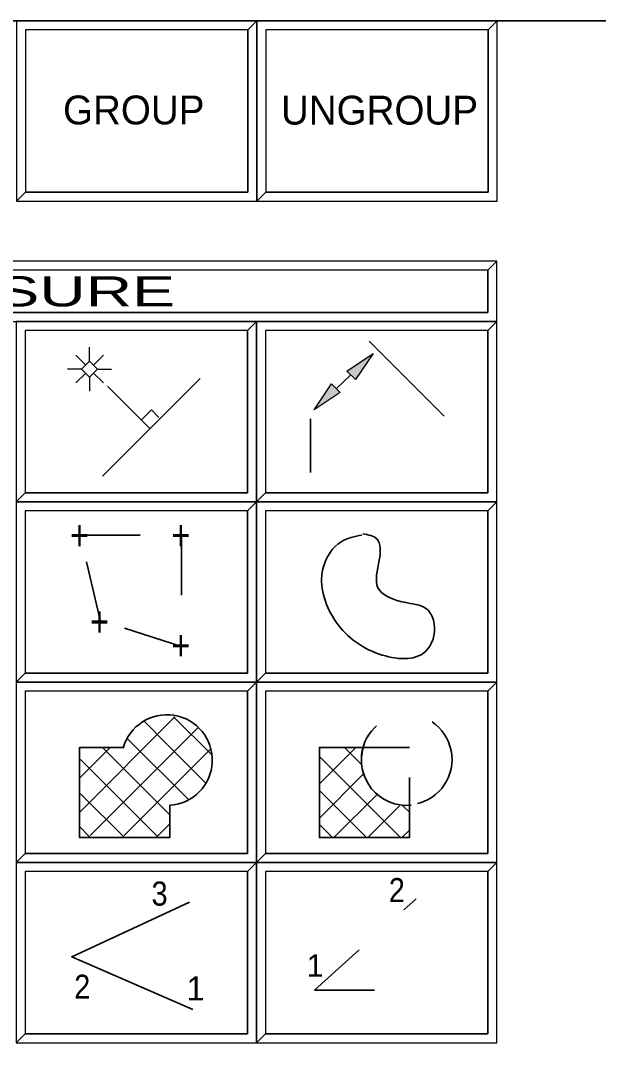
# Model space of a CAD drawing. Extents: x 95906.8 to 95923.6, y 90964.8 to 90972.8.
# Drawn here: x 95911.64 to 95912.601, y 90971.034 to 90972.762 of the extents above; entities that cross this region are included whole.
import ezdxf
from ezdxf.enums import TextEntityAlignment as Align

# ---------------------------------------------------------------- set-up
doc = ezdxf.new("R2010")
doc.units = 0
doc.header["$LTSCALE"] = 0.019
doc.linetypes.add('DOTTED', pattern=[1.5, 0.3, -1.2])
doc.linetypes.add('MEDIUM_DASHED', pattern=[4.5, 3, -1.5])
for name, color, linetype, lineweight in [('1', 7, 'Continuous', 25), ('11', 7, 'Continuous', 25), ('2', 7, 'Continuous', 13), ('21', 7, 'Continuous', 25), ('3', 7, 'Continuous', 25), ('6', 7, 'Continuous', 35), ('7', 7, 'Continuous', 35)]:
    doc.layers.add(name, color=color, linetype=linetype, lineweight=lineweight)

msp = doc.modelspace()

# ---------------------------------------------------------------- hatches: boundary and pattern name
at = {"layer": '6'}
for points in [[(95912.1824, 90972.179), (95912.2258, 90972.208), (95912.1968, 90972.1646)], [(95912.1713, 90972.1433), (95912.1279, 90972.1143), (95912.1569, 90972.1577)]]:
    msp.add_hatch(color=256, dxfattribs=at).paths.add_polyline_path(points)

# ---------------------------------------------------------------- linework, layer by layer
at = {"layer": '1'}
for points in [[(95911.6323, 90972.4617), (95912.0323, 90972.4617), (95912.0323, 90972.7617), (95911.6323, 90972.7617)], [(95912.0323, 90972.4617), (95912.4323, 90972.4617), (95912.4323, 90972.7617), (95912.0323, 90972.7617)], [(95910.8318, 90972.2615), (95912.4318, 90972.2615), (95912.4318, 90972.3615), (95910.8318, 90972.3615)], [(95911.6318, 90971.9615), (95912.0318, 90971.9615), (95912.0318, 90972.2615), (95911.6318, 90972.2615)], [(95912.0318, 90971.9615), (95912.4318, 90971.9615), (95912.4318, 90972.2615), (95912.0318, 90972.2615)], [(95911.6318, 90971.6615), (95912.0318, 90971.6615), (95912.0318, 90971.9615), (95911.6318, 90971.9615)], [(95912.0318, 90971.6615), (95912.4318, 90971.6615), (95912.4318, 90971.9615), (95912.0318, 90971.9615)], [(95911.6318, 90971.3615), (95912.0318, 90971.3615), (95912.0318, 90971.6615), (95911.6318, 90971.6615)], [(95912.0318, 90971.3615), (95912.4318, 90971.3615), (95912.4318, 90971.6615), (95912.0318, 90971.6615)], [(95911.6318, 90971.0615), (95912.0318, 90971.0615), (95912.0318, 90971.3615), (95911.6318, 90971.3615)], [(95912.0318, 90971.0615), (95912.4318, 90971.0615), (95912.4318, 90971.3615), (95912.0318, 90971.3615)]]:
    msp.add_lwpolyline(points, close=True, dxfattribs=at)
at = {"layer": '11'}
for points in [[(95911.6473, 90972.4767), (95912.0173, 90972.4767), (95912.0173, 90972.7467), (95911.6473, 90972.7467)], [(95912.0473, 90972.4767), (95912.4173, 90972.4767), (95912.4173, 90972.7467), (95912.0473, 90972.7467)], [(95911.6468, 90971.9765), (95912.0168, 90971.9765), (95912.0168, 90972.2465), (95911.6468, 90972.2465)], [(95912.0468, 90971.9765), (95912.4168, 90971.9765), (95912.4168, 90972.2465), (95912.0468, 90972.2465)], [(95911.6468, 90971.6765), (95912.0168, 90971.6765), (95912.0168, 90971.9465), (95911.6468, 90971.9465)], [(95912.0468, 90971.6765), (95912.4168, 90971.6765), (95912.4168, 90971.9465), (95912.0468, 90971.9465)], [(95911.6468, 90971.3765), (95912.0168, 90971.3765), (95912.0168, 90971.6465), (95911.6468, 90971.6465)], [(95912.0468, 90971.3765), (95912.4168, 90971.3765), (95912.4168, 90971.6465), (95912.0468, 90971.6465)], [(95911.6468, 90971.0765), (95912.0168, 90971.0765), (95912.0168, 90971.3465), (95911.6468, 90971.3465)], [(95912.0468, 90971.0765), (95912.4168, 90971.0765), (95912.4168, 90971.3465), (95912.0468, 90971.3465)]]:
    msp.add_lwpolyline(points, close=True, dxfattribs=at)
at = {"layer": '2'}
for points in [[(95911.6323, 90972.7617), (95911.6323, 90972.4617), (95911.6473, 90972.4767), (95911.6473, 90972.7467), (95912.0173, 90972.7467), (95912.0323, 90972.7617)], [(95912.0323, 90972.7617), (95912.0323, 90972.4617), (95912.0473, 90972.4767), (95912.0473, 90972.7467), (95912.4173, 90972.7467), (95912.4323, 90972.7617)], [(95910.8318, 90972.3615), (95910.8318, 90972.2615), (95910.8468, 90972.2765), (95910.8468, 90972.3465), (95912.4168, 90972.3465), (95912.4318, 90972.3615)], [(95911.6318, 90972.2615), (95911.6318, 90971.9615), (95911.6468, 90971.9765), (95911.6468, 90972.2465), (95912.0168, 90972.2465), (95912.0318, 90972.2615)], [(95912.0318, 90972.2615), (95912.0318, 90971.9615), (95912.0468, 90971.9765), (95912.0468, 90972.2465), (95912.4168, 90972.2465), (95912.4318, 90972.2615)], [(95911.6318, 90971.9615), (95911.6318, 90971.6615), (95911.6468, 90971.6765), (95911.6468, 90971.9465), (95912.0168, 90971.9465), (95912.0318, 90971.9615)], [(95912.0318, 90971.9615), (95912.0318, 90971.6615), (95912.0468, 90971.6765), (95912.0468, 90971.9465), (95912.4168, 90971.9465), (95912.4318, 90971.9615)], [(95911.6318, 90971.6615), (95911.6318, 90971.3615), (95911.6468, 90971.3765), (95911.6468, 90971.6465), (95912.0168, 90971.6465), (95912.0318, 90971.6615)], [(95912.0318, 90971.6615), (95912.0318, 90971.3615), (95912.0468, 90971.3765), (95912.0468, 90971.6465), (95912.4168, 90971.6465), (95912.4318, 90971.6615)], [(95911.6318, 90971.3615), (95911.6318, 90971.0615), (95911.6468, 90971.0765), (95911.6468, 90971.3465), (95912.0168, 90971.3465), (95912.0318, 90971.3615)], [(95912.0318, 90971.3615), (95912.0318, 90971.0615), (95912.0468, 90971.0765), (95912.0468, 90971.3465), (95912.4168, 90971.3465), (95912.4318, 90971.3615)]]:
    msp.add_lwpolyline(points, close=True, dxfattribs=at)
at = {"layer": '21'}
msp.add_lwpolyline([(95910.8468, 90972.2765), (95912.4168, 90972.2765), (95912.4168, 90972.3465), (95910.8468, 90972.3465)], close=True, dxfattribs=at)
at = {"layer": '3'}
for points in [[(95911.6323, 90972.4617), (95912.0323, 90972.4617), (95912.0323, 90972.7617), (95912.0173, 90972.7467), (95912.0173, 90972.4767), (95911.6473, 90972.4767)], [(95912.0323, 90972.4617), (95912.4323, 90972.4617), (95912.4323, 90972.7617), (95912.4173, 90972.7467), (95912.4173, 90972.4767), (95912.0473, 90972.4767)], [(95910.8318, 90972.2615), (95912.4318, 90972.2615), (95912.4318, 90972.3615), (95912.4168, 90972.3465), (95912.4168, 90972.2765), (95910.8468, 90972.2765)], [(95911.6318, 90971.9615), (95912.0318, 90971.9615), (95912.0318, 90972.2615), (95912.0168, 90972.2465), (95912.0168, 90971.9765), (95911.6468, 90971.9765)], [(95912.0318, 90971.9615), (95912.4318, 90971.9615), (95912.4318, 90972.2615), (95912.4168, 90972.2465), (95912.4168, 90971.9765), (95912.0468, 90971.9765)], [(95911.6318, 90971.6615), (95912.0318, 90971.6615), (95912.0318, 90971.9615), (95912.0168, 90971.9465), (95912.0168, 90971.6765), (95911.6468, 90971.6765)], [(95912.0318, 90971.6615), (95912.4318, 90971.6615), (95912.4318, 90971.9615), (95912.4168, 90971.9465), (95912.4168, 90971.6765), (95912.0468, 90971.6765)], [(95911.6318, 90971.3615), (95912.0318, 90971.3615), (95912.0318, 90971.6615), (95912.0168, 90971.6465), (95912.0168, 90971.3765), (95911.6468, 90971.3765)], [(95912.0318, 90971.3615), (95912.4318, 90971.3615), (95912.4318, 90971.6615), (95912.4168, 90971.6465), (95912.4168, 90971.3765), (95912.0468, 90971.3765)], [(95911.6318, 90971.0615), (95912.0318, 90971.0615), (95912.0318, 90971.3615), (95912.0168, 90971.3465), (95912.0168, 90971.0765), (95911.6468, 90971.0765)], [(95912.0318, 90971.0615), (95912.4318, 90971.0615), (95912.4318, 90971.3615), (95912.4168, 90971.3465), (95912.4168, 90971.0765), (95912.0468, 90971.0765)]]:
    msp.add_lwpolyline(points, close=True, dxfattribs=at)
at = {"layer": '6', "lineweight": 25}
for p, q in [((95911.7542, 90972.1955), (95911.7542, 90972.2189)), ((95911.741, 90972.1822), (95911.7175, 90972.1822)), ((95911.7674, 90972.1822), (95911.7908, 90972.1822)), ((95911.7542, 90972.169), (95911.7542, 90972.1456))]:
    msp.add_line(p, q, dxfattribs=at)
at = {"layer": '6'}
for p, q in [((95912.2195, 90972.2288), (95912.3444, 90972.1038)), ((95911.9382, 90972.1663), (95911.7758, 90972.0039)), ((95912.165, 90972.1498), (95912.189, 90972.1728)), ((95911.7841, 90972.1538), (95911.8549, 90972.083)), ((95912.1216, 90972.0101), (95912.1216, 90972.0997)), ((95911.8109, 90971.5527), (95911.7378, 90971.5527))]:
    msp.add_line(p, q, dxfattribs=at)
at = {"layer": '6', "linetype": 'MEDIUM_DASHED', "lineweight": 13}
for p, q in [((95911.7476, 90972.1888), (95911.731, 90972.2054)), ((95911.7608, 90972.1888), (95911.7774, 90972.2054)), ((95911.7476, 90972.1756), (95911.731, 90972.1591)), ((95911.7608, 90972.1756), (95911.7774, 90972.1591))]:
    msp.add_line(p, q, dxfattribs=at)
at = {"layer": '6', "lineweight": 13}
for p, q in [((95911.7376, 90971.4453), (95911.896, 90971.6037)), ((95911.8442, 90971.5969), (95911.884, 90971.5571)), ((95911.8939, 90971.6037), (95911.9574, 90971.5402)), ((95911.7552, 90971.4063), (95911.9341, 90971.5851)), ((95911.8179, 90971.5667), (95911.9187, 90971.4659)), ((95911.7373, 90971.5015), (95911.788, 90971.5522)), ((95911.7755, 90971.5526), (95911.8882, 90971.4401)), ((95911.8119, 90971.4064), (95911.9564, 90971.5509)), ((95911.8845, 90971.5566), (95911.9477, 90971.4934)), ((95912.1375, 90971.4927), (95912.1967, 90971.5519)), ((95912.1786, 90971.5524), (95912.2073, 90971.5237)), ((95911.7389, 90971.5325), (95911.8665, 90971.4049)), ((95912.1369, 90971.5375), (95912.2717, 90971.4027)), ((95912.1365, 90971.4351), (95912.2102, 90971.5088)), ((95911.739, 90971.4758), (95911.812, 90971.4028)), ((95912.1364, 90971.4814), (95912.2151, 90971.4027)), ((95912.1612, 90971.4033), (95912.2319, 90971.4741)), ((95912.2748, 90971.4564), (95912.2875, 90971.4437)), ((95912.2179, 90971.4034), (95912.2701, 90971.4555)), ((95911.8657, 90971.4037), (95911.8877, 90971.4257)), ((95912.1368, 90971.4244), (95912.1587, 90971.4025)), ((95911.7371, 90971.4211), (95911.7545, 90971.4037)), ((95912.2735, 90971.4025), (95912.2869, 90971.4159))]:
    msp.add_line(p, q, dxfattribs=at)
at = {"layer": '6', "linetype": 'MEDIUM_DASHED'}
for q in [(95912.2978, 90971.3009), (95912.3182, 90971.149)]:
    msp.add_line((95912.1283, 90971.149), q, dxfattribs=at)
at = {"layer": '6', "lineweight": 25}
for points in [[(95912.1824, 90972.179), (95912.2258, 90972.208), (95912.1968, 90972.1646)], [(95912.1713, 90972.1433), (95912.1279, 90972.1143), (95912.1569, 90972.1577)]]:
    msp.add_lwpolyline(points, close=True, dxfattribs=at)
at = {"layer": '6', "lineweight": 13}
msp.add_lwpolyline([(95911.7542, 90972.169), (95911.7675, 90972.1823), (95911.7542, 90972.1955), (95911.7409, 90972.1823)], close=True, dxfattribs=at)
msp.add_lwpolyline([(95911.8404, 90972.0976), (95911.8571, 90972.1143), (95911.8695, 90972.1018)], dxfattribs=at)
at = {"layer": '6', "linetype": 'MEDIUM_DASHED'}
msp.add_lwpolyline([(95911.7383, 90971.906), (95911.9071, 90971.906), (95911.9071, 90971.7206), (95911.7717, 90971.7643)], close=True, dxfattribs=at)
at = {"layer": '6'}
for points in [[(95911.7374, 90971.553), (95911.7374, 90971.4027), (95911.8874, 90971.4027), (95911.8874, 90971.4565)], [(95912.2114, 90971.5527), (95912.1365, 90971.5527), (95912.1365, 90971.4027), (95912.2865, 90971.4027), (95912.2865, 90971.4586)], [(95911.9202, 90971.2951), (95911.7245, 90971.2045), (95911.9261, 90971.1169)]]:
    msp.add_lwpolyline(points, dxfattribs=at)
at = {"layer": '6', "linetype": 'DOTTED'}
msp.add_lwpolyline([(95912.1365, 90971.4027), (95912.2865, 90971.4027), (95912.2865, 90971.5527), (95912.1365, 90971.5527)], close=True, dxfattribs=at)
msp.add_circle((95912.2819, 90971.5326), 0.0754, dxfattribs=at)
at = {"layer": '6'}
for centre, start, end in [((95911.8828, 90971.5317), 273.8644, 164.6109), ((95912.2819, 90971.5317), 162.9658, 275.5202)]:
    msp.add_arc(centre, 0.0754, start, end, dxfattribs=at)
msp.add_spline([(95912.207, 90971.906), (95912.1737, 90971.8956), (95912.1424, 90971.8497), (95912.1612, 90971.7664), (95912.2362, 90971.7081), (95912.3132, 90971.7123), (95912.3278, 90971.7581), (95912.3174, 90971.781), (95912.2716, 90971.7956), (95912.2341, 90971.8185), (95912.2362, 90971.8643), (95912.232, 90971.8997), (95912.2091, 90971.9081)], degree=3, dxfattribs=at)
at = {"layer": '7'}
msp.add_lwpolyline([(95906.8323, 90972.7617), (95918.8323, 90972.7617), (95918.8323, 90964.7617), (95906.8323, 90964.7617)], close=True, dxfattribs=at)

# ---------------------------------------------------------------- texts
at = {"layer": '21', "width": 1.6}
msp.add_text('        MEASURE        ', height=0.04999, dxfattribs=at).set_placement((95911.6318, 90972.2865), align=Align.CENTER)
at = {"layer": '6'}
for s, height, p in [('GROUP', 0.048, (95911.8276, 90972.5893)), ('UNGROUP', 0.048, (95912.2366, 90972.589)), ('1', 0.0375, (95912.1295, 90971.1711)), ('1', 0.04, (95911.9305, 90971.1318))]:
    msp.add_text(s, height=height, dxfattribs=at).set_placement(p, align=Align.CENTER)
at = {"layer": '6', "width": 0.8}
for p in [(95911.7217, 90971.881), (95911.8904, 90971.881), (95911.755, 90971.7373), (95911.8904, 90971.6977)]:
    msp.add_text('+', height=0.05, dxfattribs=at).set_placement(p)
at = {"layer": '6', "width": 0.9}
for s, p in [('2', (95912.2655, 90971.2954)), ('3', (95911.8706, 90971.2896)), ('2', (95911.7419, 90971.1347))]:
    msp.add_text(s, height=0.04, dxfattribs=at).set_placement(p, align=Align.CENTER)

doc.saveas('drawing.dxf')
